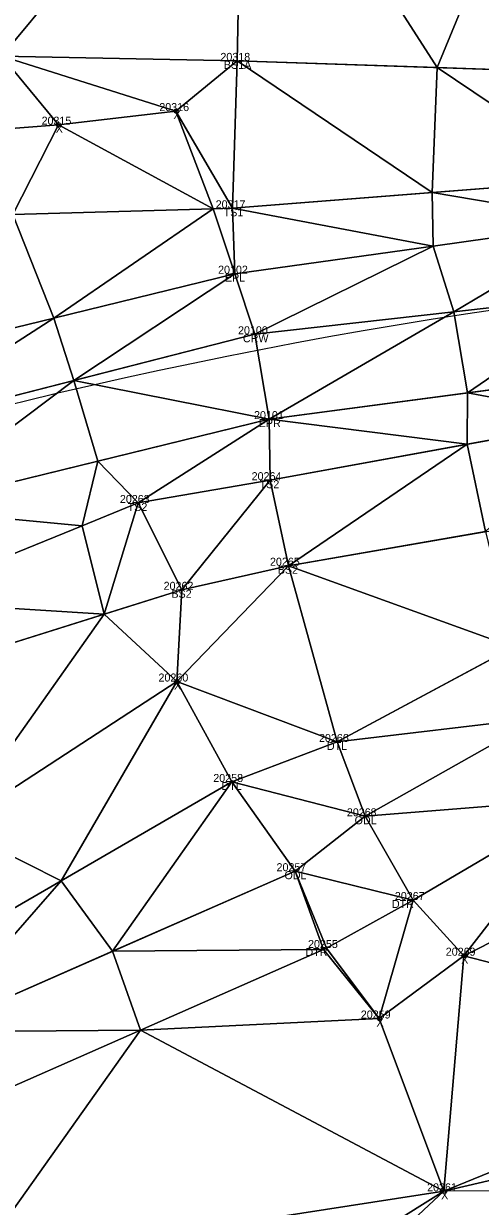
# Model space of a CAD drawing. Extents: x 1966740 to 1969291, y 1117379 to 1118460.
# Drawn here: x 1967940 to 1967997, y 1117812.4 to 1117960.2 of the extents above; entities that cross this region are included whole.
import ezdxf

# ---------------------------------------------------------------- set-up
doc = ezdxf.new("R2010")
doc.units = 0
for name, color, linetype in [('Level 1', 7, 'Continuous'), ('Level 10', 7, 'Continuous'), ('Level 3', 7, 'Continuous'), ('Level 30', 7, 'Continuous'), ('Level 35', 7, 'Continuous'), ('Level 50', 7, 'Continuous'), ('Level 52', 7, 'Continuous'), ('Level 53', 7, 'Continuous'), ('Level 56', 7, 'Continuous'), ('Level 6', 7, 'Continuous'), ('Level 60', 7, 'Continuous'), ('Level 61', 7, 'Continuous'), ('Level 62', 7, 'Continuous')]:
    doc.layers.add(name, color=color, linetype=linetype)

msp = doc.modelspace()

# ---------------------------------------------------------------- linework, layer by layer
at = {"layer": 'Level 1'}
msp.add_arc((1968094.39, 1117277.53), 653.93, 87.72663, 111.99584, dxfattribs=at)
at = {"layer": 'Level 10'}
for points in [[(1967872.82, 1117824.49), (1967892.16, 1117820.53), (1967923.08, 1117840.53), (1967966.02, 1117865.44), (1967979.17, 1117870.44), (1968016.32, 1117890.41), (1968058.49, 1117903.84)], [(1967873.55, 1117813.3), (1967887.27, 1117810.69), (1967931.74, 1117824.33), (1967977.85, 1117844.69), (1967988.67, 1117850.69), (1968023.3, 1117871.08), (1968058.02, 1117883.74)]]:
    msp.add_lwpolyline(points, dxfattribs=at)
at = {"layer": 'Level 3'}
for points in [[(1967966.69, 1117955.54), (1968012.01, 1117954.01), (1968059.56, 1117952.62), (1968105.42, 1117949)], [(1967874.77, 1117908.42), (1967879.51, 1117916.91), (1967881.27, 1117924.39), (1967885.24, 1117929.22), (1967913.7, 1117935.63), (1967966.11, 1117937.12), (1968012.39, 1117940.75), (1968059.42, 1117941.87), (1968105.44, 1117943.27), (1968158.32, 1117942.95), (1968212.48, 1117942.1), (1968371.25, 1117933.41), (1968422.85, 1117933.68), (1968531.49, 1117931.42)], [(1967878.98, 1117895.46), (1967875.66, 1117903.48), (1967919.49, 1117917.47), (1967966.4, 1117928.95), (1968012.66, 1117935.42), (1968058.94, 1117938.37), (1968105.99, 1117939.39), (1968158.7, 1117938.56), (1968212.05, 1117937.21), (1968318.79, 1117933.28), (1968422.76, 1117929.93), (1968530.54, 1117925.7)], [(1967878.98, 1117895.46), (1967922.07, 1117909.4), (1967968.89, 1117921.38), (1968013.49, 1117926.44), (1968059.29, 1117929.05), (1968105.63, 1117929.86), (1968159.12, 1117928.97), (1968212.65, 1117927.25), (1968318.5, 1117923.95), (1968422.42, 1117919.39), (1968529.36, 1117916.3)], [(1967878.98, 1117895.46), (1967883.11, 1117885.63), (1967924.99, 1117899.59), (1967970.68, 1117910.78), (1968014.42, 1117916.56), (1968059.13, 1117919.49), (1968105.39, 1117920.31), (1968159.16, 1117919.37), (1968212.5, 1117917.97), (1968317.55, 1117914.44), (1968421.52, 1117910.75), (1968527.82, 1117906.41)], [(1967884.1, 1117882.92), (1967891.06, 1117879.24), (1967898.84, 1117879.11), (1967924.17, 1117888.04), (1967954.33, 1117900.3), (1967970.81, 1117903.15), (1968012.93, 1117910.83), (1968059.62, 1117915.05), (1968105.25, 1117916.2), (1968157.57, 1117912.09), (1968210.74, 1117910.77), (1968320.32, 1117907.54), (1968423.18, 1117904.83), (1968528.99, 1117899.6)], [(1967864, 1117905.28), (1967874.64, 1117878.97), (1967881.18, 1117873.82), (1967887.49, 1117871.9), (1967896.22, 1117872.02), (1967926.22, 1117878.93), (1967959.79, 1117889.45), (1967973.08, 1117892.46), (1968014.67, 1117899.65), (1968058.49, 1117903.84)]]:
    msp.add_lwpolyline(points, dxfattribs=at)
at = {"layer": 'Level 30'}
for centre in [(1967959.04, 1117949.27), (1967944.36, 1117947.57), (1967959.15, 1117877.99), (1967995, 1117843.73), (1967984.42, 1117835.88), (1967992.48, 1117814.29)]:
    msp.add_circle(centre, 0.25, dxfattribs=at)
at = {"layer": 'Level 35'}
for points in [[(1967924.02, 1117977.55), (1967967.44, 1117992.51), (1967937.28, 1117956.15)], [(1967937.28, 1117956.15), (1967967.44, 1117992.51), (1967966.69, 1117955.54)], [(1967966.69, 1117955.54), (1967967.44, 1117992.51), (1967991.67, 1117954.7)], [(1967967.44, 1117992.51), (1968007.64, 1117993.49), (1967991.67, 1117954.7)], [(1967991.67, 1117954.7), (1968007.64, 1117993.49), (1968012.01, 1117954.01)], [(1967930.94, 1117946.51), (1967937.28, 1117956.15), (1967944.36, 1117947.57)], [(1967937.28, 1117956.15), (1967966.69, 1117955.54), (1967959.04, 1117949.27)], [(1967937.28, 1117956.15), (1967959.04, 1117949.27), (1967944.36, 1117947.57)], [(1967959.04, 1117949.27), (1967966.69, 1117955.54), (1967966.11, 1117937.12)], [(1967966.11, 1117937.12), (1967966.69, 1117955.54), (1967991.03, 1117939.08)], [(1967966.69, 1117955.54), (1967991.67, 1117954.7), (1967991.03, 1117939.08)], [(1967991.03, 1117939.08), (1967991.67, 1117954.7), (1968012.39, 1117940.75)], [(1967991.67, 1117954.7), (1968012.01, 1117954.01), (1968012.39, 1117940.75)], [(1967944.36, 1117947.57), (1967959.04, 1117949.27), (1967963.68, 1117937.05)], [(1967959.04, 1117949.27), (1967966.11, 1117937.12), (1967963.68, 1117937.05)], [(1967930.94, 1117946.51), (1967944.36, 1117947.57), (1967938.69, 1117936.34)], [(1967938.69, 1117936.34), (1967944.36, 1117947.57), (1967963.68, 1117937.05)], [(1967991.03, 1117939.08), (1968012.39, 1117940.75), (1968012.66, 1117935.42)], [(1967966.11, 1117937.12), (1967991.03, 1117939.08), (1967991.16, 1117932.41)], [(1967991.03, 1117939.08), (1968012.66, 1117935.42), (1967991.16, 1117932.41)], [(1967919.49, 1117917.47), (1967938.69, 1117936.34), (1967943.77, 1117923.41)], [(1967938.69, 1117936.34), (1967963.68, 1117937.05), (1967943.77, 1117923.41)], [(1967943.77, 1117923.41), (1967963.68, 1117937.05), (1967966.4, 1117928.95)], [(1967963.68, 1117937.05), (1967966.11, 1117937.12), (1967966.4, 1117928.95)], [(1967966.11, 1117937.12), (1967991.16, 1117932.41), (1967966.4, 1117928.95)], [(1967991.16, 1117932.41), (1968012.66, 1117935.42), (1967993.73, 1117924.19)], [(1967993.73, 1117924.19), (1968012.66, 1117935.42), (1968013.49, 1117926.44)], [(1967966.4, 1117928.95), (1967991.16, 1117932.41), (1967968.89, 1117921.38)], [(1967968.89, 1117921.38), (1967991.16, 1117932.41), (1967993.73, 1117924.19)], [(1967943.77, 1117923.41), (1967966.4, 1117928.95), (1967946.28, 1117915.6)], [(1967946.28, 1117915.6), (1967966.4, 1117928.95), (1967968.89, 1117921.38)], [(1967993.73, 1117924.19), (1968013.49, 1117926.44), (1967995.46, 1117914.05)], [(1967995.46, 1117914.05), (1968013.49, 1117926.44), (1968014.42, 1117916.56)], [(1967968.89, 1117921.38), (1967993.73, 1117924.19), (1967970.68, 1117910.78)], [(1967970.68, 1117910.78), (1967993.73, 1117924.19), (1967995.46, 1117914.05)], [(1967919.49, 1117917.47), (1967943.77, 1117923.41), (1967922.07, 1117909.4)], [(1967922.07, 1117909.4), (1967943.77, 1117923.41), (1967946.28, 1117915.6)], [(1967946.28, 1117915.6), (1967968.89, 1117921.38), (1967970.68, 1117910.78)], [(1967922.07, 1117909.4), (1967946.28, 1117915.6), (1967924.99, 1117899.59)], [(1967924.99, 1117899.59), (1967946.28, 1117915.6), (1967949.27, 1117905.54)], [(1967946.28, 1117915.6), (1967970.68, 1117910.78), (1967949.27, 1117905.54)], [(1967995.46, 1117914.05), (1968014.42, 1117916.56), (1968012.93, 1117910.83)], [(1967970.68, 1117910.78), (1967995.46, 1117914.05), (1967995.41, 1117907.63)], [(1967995.41, 1117907.63), (1967995.46, 1117914.05), (1968012.93, 1117910.83)], [(1967995.41, 1117907.63), (1968012.93, 1117910.83), (1967997.71, 1117896.72)], [(1967949.27, 1117905.54), (1967970.68, 1117910.78), (1967954.33, 1117900.3)], [(1967954.33, 1117900.3), (1967970.68, 1117910.78), (1967970.81, 1117903.15)], [(1967970.68, 1117910.78), (1967995.41, 1117907.63), (1967970.81, 1117903.15)], [(1967970.81, 1117903.15), (1967995.41, 1117907.63), (1967973.08, 1117892.46)], [(1967973.08, 1117892.46), (1967995.41, 1117907.63), (1967997.71, 1117896.72)], [(1967924.99, 1117899.59), (1967949.27, 1117905.54), (1967947.33, 1117897.45)], [(1967947.33, 1117897.45), (1967949.27, 1117905.54), (1967954.33, 1117900.3)], [(1967954.33, 1117900.3), (1967970.81, 1117903.15), (1967959.79, 1117889.45)], [(1967959.79, 1117889.45), (1967970.81, 1117903.15), (1967973.08, 1117892.46)], [(1967924.17, 1117888.04), (1967924.99, 1117899.59), (1967947.33, 1117897.45)], [(1967947.33, 1117897.45), (1967954.33, 1117900.3), (1967950.07, 1117886.41)], [(1967950.07, 1117886.41), (1967954.33, 1117900.3), (1967959.79, 1117889.45)], [(1967924.17, 1117888.04), (1967947.33, 1117897.45), (1967950.07, 1117886.41)], [(1967973.08, 1117892.46), (1967997.71, 1117896.72), (1968001.19, 1117882.28)], [(1967959.15, 1117877.99), (1967959.79, 1117889.45), (1967973.08, 1117892.46)], [(1967959.15, 1117877.99), (1967973.08, 1117892.46), (1967979.17, 1117870.44)], [(1967973.08, 1117892.46), (1968001.19, 1117882.28), (1967979.17, 1117870.44)], [(1967950.07, 1117886.41), (1967959.79, 1117889.45), (1967959.15, 1117877.99)], [(1967924.17, 1117888.04), (1967950.07, 1117886.41), (1967926.22, 1117878.93)], [(1967926.22, 1117878.93), (1967950.07, 1117886.41), (1967931.3, 1117859.84)], [(1967931.3, 1117859.84), (1967950.07, 1117886.41), (1967959.15, 1117877.99)], [(1967979.17, 1117870.44), (1968001.19, 1117882.28), (1968004.43, 1117873.47)], [(1967931.3, 1117859.84), (1967959.15, 1117877.99), (1967944.7, 1117853.07)], [(1967944.7, 1117853.07), (1967959.15, 1117877.99), (1967966.02, 1117865.44)], [(1967959.15, 1117877.99), (1967979.17, 1117870.44), (1967966.02, 1117865.44)], [(1967979.17, 1117870.44), (1968004.43, 1117873.47), (1967982.67, 1117861.15)], [(1967982.67, 1117861.15), (1968004.43, 1117873.47), (1968010.21, 1117863.37)], [(1967966.02, 1117865.44), (1967979.17, 1117870.44), (1967982.67, 1117861.15)], [(1967944.7, 1117853.07), (1967966.02, 1117865.44), (1967951.12, 1117844.28)], [(1967951.12, 1117844.28), (1967966.02, 1117865.44), (1967973.92, 1117854.29)], [(1967966.02, 1117865.44), (1967982.67, 1117861.15), (1967973.92, 1117854.29)], [(1967982.67, 1117861.15), (1968010.21, 1117863.37), (1967988.67, 1117850.69)], [(1967988.67, 1117850.69), (1968010.21, 1117863.37), (1967995, 1117843.73)], [(1967995, 1117843.73), (1968010.21, 1117863.37), (1968026.29, 1117859.51)], [(1967973.92, 1117854.29), (1967982.67, 1117861.15), (1967988.67, 1117850.69)], [(1967923.08, 1117840.53), (1967931.3, 1117859.84), (1967944.7, 1117853.07)], [(1967995, 1117843.73), (1968026.29, 1117859.51), (1968037.48, 1117832.72)], [(1967951.12, 1117844.28), (1967973.92, 1117854.29), (1967977.45, 1117844.52)], [(1967973.92, 1117854.29), (1967988.67, 1117850.69), (1967977.85, 1117844.69)], [(1967973.92, 1117854.29), (1967977.85, 1117844.69), (1967977.45, 1117844.52)], [(1967923.08, 1117840.53), (1967944.7, 1117853.07), (1967928.24, 1117834.22)], [(1967928.24, 1117834.22), (1967944.7, 1117853.07), (1967951.12, 1117844.28)], [(1967977.85, 1117844.69), (1967988.67, 1117850.69), (1967984.42, 1117835.88)], [(1967984.42, 1117835.88), (1967988.67, 1117850.69), (1967995, 1117843.73)], [(1967951.12, 1117844.28), (1967977.45, 1117844.52), (1967954.6, 1117834.42)], [(1967954.6, 1117834.42), (1967977.45, 1117844.52), (1967984.42, 1117835.88)], [(1967977.45, 1117844.52), (1967977.85, 1117844.69), (1967984.42, 1117835.88)], [(1967928.24, 1117834.22), (1967951.12, 1117844.28), (1967954.6, 1117834.42)], [(1967984.42, 1117835.88), (1967995, 1117843.73), (1967992.48, 1117814.29)], [(1967992.48, 1117814.29), (1967995, 1117843.73), (1968037.48, 1117832.72)], [(1967954.6, 1117834.42), (1967984.42, 1117835.88), (1967992.48, 1117814.29)], [(1967928.24, 1117834.22), (1967954.6, 1117834.42), (1967931.74, 1117824.33)], [(1967931.74, 1117824.33), (1967954.6, 1117834.42), (1967933.88, 1117805.22)], [(1967933.88, 1117805.22), (1967954.6, 1117834.42), (1967992.48, 1117814.29)], [(1967992.48, 1117814.29), (1968037.48, 1117832.72), (1968072.17, 1117832.89)], [(1967992.48, 1117814.29), (1968072.17, 1117832.89), (1968144.42, 1117814.73)], [(1967909.99, 1117737.2), (1967943.66, 1117783.72), (1967992.48, 1117814.29)], [(1967933.88, 1117805.22), (1967992.48, 1117814.29), (1967943.66, 1117783.72)]]:
    msp.add_lwpolyline(points, close=True, dxfattribs=at)
at = {"layer": 'Level 50'}
for centre in [(1967966.69, 1117955.54), (1967966.11, 1117937.12), (1967966.4, 1117928.95), (1967968.89, 1117921.38), (1967970.68, 1117910.78), (1967970.81, 1117903.15), (1967954.33, 1117900.3), (1967973.08, 1117892.46), (1967959.79, 1117889.45), (1967979.17, 1117870.44), (1967966.02, 1117865.44), (1967982.67, 1117861.15), (1967973.92, 1117854.29), (1967988.67, 1117850.69), (1967977.85, 1117844.69)]:
    msp.add_circle(centre, 0.001, dxfattribs=at)
at = {"layer": 'Level 6'}
msp.add_lwpolyline([(1967868.28, 1117817.14), (1967892.54, 1117814.5), (1967928.24, 1117834.22), (1967973.92, 1117854.29), (1967982.67, 1117861.15), (1968021.78, 1117883.3), (1968056.97, 1117897.44), (1968105.42, 1117898.77), (1968155.9, 1117899.84), (1968209.66, 1117898.76), (1968320.81, 1117895.57), (1968422.79, 1117894.92), (1968528.55, 1117888.35)], dxfattribs=at)

# ---------------------------------------------------------------- texts
at = {"layer": 'Level 52'}
for s, p in [('20316', (1967956.96, 1117949.27)), ('20315', (1967942.26, 1117947.57)), ('20260', (1967956.86, 1117877.99)), ('20269', (1967992.73, 1117843.73)), ('20259', (1967982.12, 1117835.88)), ('20261', (1967990.4, 1117814.29))]:
    msp.add_text(s, height=1, dxfattribs=at).set_placement(p)
at = {"layer": 'Level 53'}
for s, p in [('20318', (1967964.59, 1117955.54)), ('BS1A', (1967965.03, 1117954.54)), ('20317', (1967964, 1117937.12)), ('TS1', (1967965, 1117936.12)), ('20102', (1967964.3, 1117928.95)), ('EPL', (1967965.15, 1117927.95)), ('20100', (1967966.79, 1117921.38)), ('CRW', (1967967.4, 1117920.38)), ('20101', (1967968.79, 1117910.78)), ('EPR', (1967969.38, 1117909.78)), ('20264', (1967968.49, 1117903.15)), ('TS2', (1967969.49, 1117902.15)), ('20263', (1967952.04, 1117900.3)), ('TS2', (1967953.01, 1117899.3)), ('20265', (1967970.78, 1117892.46)), ('BS2', (1967971.75, 1117891.46)), ('20262', (1967957.5, 1117889.45)), ('BS2', (1967958.47, 1117888.45))]:
    msp.add_text(s, height=1, dxfattribs=at).set_placement(p)
at = {"layer": 'Level 56'}
for s, p in [('20268', (1967980.38, 1117861.15)), ('ODL', (1967981.35, 1117860.15)), ('20257', (1967971.6, 1117854.29)), ('ODL', (1967972.59, 1117853.29))]:
    msp.add_text(s, height=1, dxfattribs=at).set_placement(p)
at = {"layer": 'Level 60'}
for s, p in [('DTL', (1967977.89, 1117869.44)), ('DTL', (1967964.74, 1117864.44)), ('DTR', (1967986.01, 1117849.69)), ('DTR', (1967975.2, 1117843.69))]:
    msp.add_text(s, height=1, dxfattribs=at).set_placement(p)
at = {"layer": 'Level 61'}
for s, p in [('20266', (1967976.9, 1117870.44)), ('20258', (1967963.7, 1117865.44)), ('20267', (1967986.37, 1117850.69)), ('20255', (1967975.53, 1117844.69))]:
    msp.add_text(s, height=1, dxfattribs=at).set_placement(p)
at = {"layer": 'Level 62'}
for p in [(1967958.71, 1117948.27), (1967944.03, 1117946.57), (1967958.81, 1117876.99), (1967994.66, 1117842.73), (1967984.08, 1117834.88), (1967992.15, 1117813.29)]:
    msp.add_text('X', height=1, dxfattribs=at).set_placement(p)

doc.saveas('drawing.dxf')
